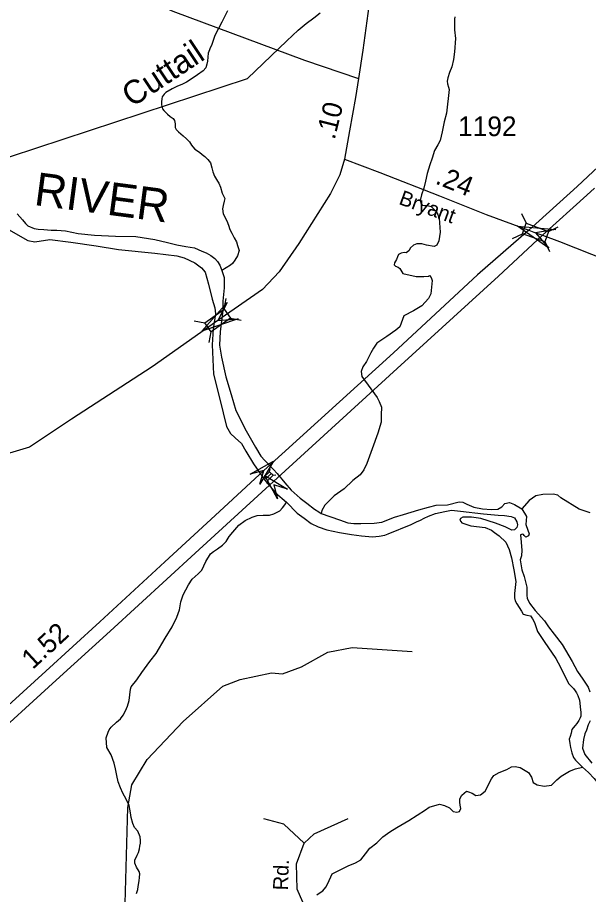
# Model space of a CAD drawing. Extents: x 2056842 to 2160602, y 826753 to 1016856.
# Drawn here: x 2102032 to 2105666, y 899934 to 905515 of the extents above; entities that cross this region are included whole.
import ezdxf

# ---------------------------------------------------------------- set-up
doc = ezdxf.new("R2010")
doc.units = 0
for name, color, linetype in [('Exist Hydrographic Creek Single Shore', 7, 'Continuous'), ('Exist Hydrographic Creek Single Shore Label', 7, 'Continuous'), ('Exist Hydrographic Misc Water Feature', 7, 'Continuous'), ('Exist Hydrographic River Shore', 7, 'Continuous'), ('Exist Hydrographic River Shore Label', 7, 'Continuous'), ('Exist Road Non-System Type 51', 7, 'Continuous'), ('Exist Road Non-System Type 51 Label', 7, 'Continuous'), ('Exist Road Primary Interstate Divided Center Attributed', 7, 'Continuous'), ('Exist Road Primary Interstate Mileage Hundredths English Label', 7, 'Continuous'), ('Exist Road Primary Interstate Structure Standard Bridge CELL', 7, 'Continuous'), ('Exist Road Secondary Mileage Hundredths English Label', 7, 'Continuous'), ('Exist Road Secondary Structure Standard Bridge Attributed CELL', 7, 'Continuous'), ('Exist Road Secondary Structure Standard Bridge CELL', 7, 'Continuous'), ('Exist Road Secondary Type 51 Attributed', 7, 'Continuous'), ('Exist Road Secondary Type 51 Label', 7, 'Continuous'), ('Exist Road Secondary Type 51 Number Label', 7, 'Continuous'), ('Exist Utilities Electrical Transmission Line', 7, 'Continuous')]:
    doc.layers.add(name, color=color, linetype=linetype)

msp = doc.modelspace()

# ---------------------------------------------------------------- linework, layer by layer
at = {"layer": 'Exist Hydrographic Creek Single Shore'}
for points in [[(2103369.4, 905558.8), (2103332, 905486.2), (2103288.3, 905400.8), (2103267.9, 905337.5), (2103258, 905321.6), (2103253.8, 905309.6), (2103245.8, 905287.4), (2103242.2, 905237.6), (2103238.1, 905217.4), (2103230.1, 905195.6), (2103214.3, 905175.6), (2103178.4, 905151.4), (2103144.4, 905127.1), (2103108.5, 905103.3), (2103078.6, 905089.1), (2103050.5, 905078.9), (2103016.7, 905060.9), (2102976.9, 905038.7), (2102964.8, 905026.5), (2102953, 905010.7), (2102950.8, 904998.6), (2102949, 904978.6), (2102949, 904958.6), (2102955, 904934.5), (2102963, 904922.5), (2102987.1, 904900.7), (2103003.2, 904884.9), (2103023.3, 904872.7), (2103031.3, 904860.7), (2103035.4, 904839), (2103035.6, 904815), (2103041.5, 904802.8), (2103057.6, 904787), (2103085.7, 904763.2), (2103107.6, 904743), (2103127.8, 904723.2), (2103139.9, 904703.3), (2103147.8, 904691.3), (2103160, 904677.3), (2103189.8, 904659.3), (2103207.9, 904643.5), (2103224, 904631.7), (2103244, 904611.6), (2103260.2, 904589.6), (2103268.1, 904557.6), (2103276.1, 904533.8), (2103286.4, 904505.7), (2103305.3, 904473.8), (2103314.3, 904461.8), (2103323.5, 904435.4), (2103335.2, 904397), (2103351.2, 904363.9), (2103348, 904345.7), (2103340.9, 904317.9), (2103337.3, 904296.7), (2103340.5, 904265.7), (2103365.2, 904221.9), (2103375.4, 904194.1), (2103383.4, 904166), (2103395.3, 904142.2), (2103411.4, 904112), (2103425.7, 904088.1), (2103431.8, 904064.3), (2103443, 904032.7), (2103432.3, 903998.5), (2103416.3, 903971.8), (2103400.3, 903950.4), (2103387.5, 903938.7), (2103333.1, 903905.6)], [(2104815.3, 905520.5), (2104813.3, 905504.5), (2104813.3, 905476.5), (2104813.1, 905435.8), (2104819.5, 905382.4), (2104813.1, 905297), (2104807.8, 905247.9), (2104796.3, 905200.5), (2104782.3, 905164.4), (2104770.4, 905132.4), (2104766.5, 905110.4), (2104768.6, 905092.4), (2104774.5, 905072.4), (2104780.5, 905056.4), (2104763.1, 904906.4), (2104747.3, 904852.3), (2104735.6, 904788.3), (2104721.6, 904732.2), (2104707.9, 904704.2), (2104685.8, 904668.2), (2104672, 904620.2), (2104656, 904578), (2104640.4, 904522.1), (2104628.5, 904474), (2104618.5, 904430), (2104602.9, 904385.9), (2104594.9, 904349.9), (2104598.8, 904333.9), (2104606.8, 904321.9), (2104623.2, 904319.2), (2104639.2, 904319.2), (2104665.8, 904312.8), (2104700, 904276.5), (2104714.9, 904239.1), (2104721.3, 904148.4), (2104713.9, 904093.9), (2104701.1, 904066.2), (2104684, 904058.7), (2104634.9, 904067.2), (2104605.6, 904074), (2104573.6, 904073.9), (2104551.9, 904065.8), (2104533.8, 904049.7), (2104521.9, 904029.7), (2104505.9, 904017.7), (2104493.8, 904019.7), (2104473.9, 904015.6), (2104457.9, 904007.6), (2104450.1, 903991.5), (2104444, 903975.5), (2104431.1, 903954.3), (2104430, 903941.5), (2104437.5, 903932.9), (2104454.6, 903925.5), (2104466.3, 903918), (2104485.5, 903887), (2104569.8, 903867.8), (2104618.9, 903867.8), (2104647.7, 903869.9), (2104655.2, 903873.1), (2104665.8, 903861.4), (2104671.2, 903841.1), (2104662.6, 903755.7), (2104648.8, 903727.9), (2104606.1, 903680.9), (2104553.1, 903647.9), (2104490.8, 903616.9), (2104465.2, 903546.4), (2104439.6, 903525.1), (2104383.1, 903484.5), (2104319.5, 903443.2), (2104297.7, 903411.9), (2104281.7, 903380.9), (2104254, 903325.4), (2104230.5, 903292.3), (2104219.8, 903261.3), (2104223, 903231.5), (2104322.2, 903096.9)], [(2104322.2, 903096.9), (2104334, 903072.4), (2104347.9, 903036.1), (2104346.8, 902987), (2104345.7, 902940), (2104325.4, 902869.7), (2104289.2, 902769.4), (2104255, 902677.5), (2104235.8, 902635.9), (2104212.3, 902603.9), (2104166.5, 902568.8), (2104111, 902516.5), (2104048, 902471.7), (2103988.3, 902411.9), (2103969.1, 902378.2), (2103965, 902358.2)], [(2103936.5, 899932.4), (2103958.6, 899946.5), (2103974.6, 899956.5), (2103994.3, 899980.6), (2104006.4, 900004.7), (2104034.1, 900064.7), (2104137.6, 900116.4), (2104183.5, 900135.6), (2104216.6, 900153.7), (2104246.5, 900192.2), (2104275.3, 900229.5), (2104319, 900262.6), (2104357.5, 900300), (2104401.3, 900331.8), (2104447.1, 900359.8), (2104523.1, 900404.1), (2104629.6, 900471.9), (2104652, 900489), (2104718.6, 900508.8), (2104750.5, 900500.9), (2104782.2, 900484.7), (2104805.6, 900461.2), (2104828, 900458), (2104845.1, 900462.3), (2104853.6, 900481.5), (2104850.4, 900502.9), (2104848.3, 900521), (2104848.3, 900543.4), (2104860.1, 900565.9), (2104888.9, 900590.4), (2104901.7, 900587.4), (2104925.1, 900577.8), (2104949.7, 900562.9), (2104979.6, 900568.2), (2105008.4, 900590.6), (2105048.9, 900669.6), (2105063.9, 900692.1), (2105098, 900710.2), (2105147.1, 900728.4), (2105177, 900745.4), (2105199.4, 900748.6), (2105231.4, 900741.2), (2105283.7, 900711.3), (2105304, 900681.4), (2105314.6, 900646.1), (2105339.2, 900631.2), (2105384, 900622.7), (2105430.9, 900630.1), (2105464, 900664.3), (2105491.8, 900686.7), (2105546.2, 900717.7), (2105584.6, 900732.6), (2105628.4, 900744.4)]]:
    msp.add_lwpolyline(points, dxfattribs=at)
at = {"layer": 'Exist Hydrographic Misc Water Feature'}
for points in [[(2105676.4, 902363.4), (2105606, 902385.8), (2105489.6, 902458.4), (2105470.4, 902474.5), (2105440.5, 902480.8), (2105375.5, 902478.7), (2105331.7, 902470), (2105288, 902441.2), (2105241, 902388.8)], [(2102788.6, 899940.9), (2102798.7, 899964.9), (2102800.5, 899984.9), (2102806.4, 900021), (2102808.3, 900041), (2102810.3, 900064.9), (2102806.4, 900080.8), (2102790, 900108.8), (2102780, 900132.8), (2102778.2, 900152.8), (2102793.9, 900184.9), (2102801.9, 900200.9), (2102807.9, 900224.9), (2102811.8, 900240.9), (2102815.7, 900261), (2102815.7, 900276.9), (2102813.6, 900300.9), (2102797.4, 900336.8), (2102777.3, 900360.7), (2102767.3, 900384.7), (2102755.2, 900424.7), (2102751.1, 900452.7), (2102742.9, 900500.6), (2102722.8, 900540.6), (2102702.7, 900578.5), (2102686.7, 900612.4), (2102672.5, 900650.5), (2102664.3, 900690.4), (2102656.4, 900734.3), (2102648.1, 900770.3), (2102628.1, 900822.2), (2102601.8, 900870.2), (2102595.7, 900930.2), (2102609.6, 900966.1), (2102615.5, 900982.1), (2102627.4, 900998.2), (2102663.3, 901030.3), (2102687.3, 901052.5), (2102705.2, 901074.4), (2102719.5, 901102.9), (2102732.3, 901132.8), (2102741.9, 901169.1), (2102750.4, 901239.6), (2102754.7, 901255.6), (2102792, 901299.4), (2102823, 901347.4), (2102875.3, 901416), (2102914.8, 901467.2), (2102971.3, 901565.4), (2103016.1, 901638), (2103047.1, 901697.8), (2103063.1, 901745.9), (2103072.7, 901796.1), (2103086.8, 901841.6), (2103120.6, 901905.6), (2103144.4, 901941.7), (2103182.3, 901973.9), (2103206.3, 901997.9), (2103230.1, 902053.9), (2103259.8, 902102), (2103279.9, 902116.2), (2103305.8, 902134.2), (2103335.9, 902156.3), (2103359.7, 902180.4), (2103379.6, 902212.4), (2103403.6, 902240.4), (2103441.3, 902284.6), (2103481.3, 902314.7), (2103526.2, 902335.7), (2103557.1, 902346.3), (2103596.6, 902348.5), (2103619, 902347.4), (2103636.1, 902348.5), (2103662.8, 902357), (2103701.1, 902375.4), (2103719.1, 902395.5), (2103732.9, 902413.5), (2103744.8, 902431.6)]]:
    msp.add_lwpolyline(points, dxfattribs=at)
at = {"layer": 'Exist Hydrographic River Shore'}
for points in [[(2102030.2, 904264.8), (2102064.3, 904227.4), (2102083.5, 904205), (2102098.5, 904190), (2102139, 904173), (2102163.5, 904168.7), (2102199.8, 904166.1), (2102246.8, 904161.9), (2102282, 904160.8), (2102337.5, 904158.6), (2102417.5, 904140.5), (2102523.1, 904130.9), (2102655.5, 904123.4), (2102784.6, 904121.3), (2102906.2, 904102.1), (2102987.3, 904083.9), (2103047.1, 904069), (2103103.6, 904058.3), (2103158.1, 904048.7), (2103205.9, 904027.7), (2103233.9, 904017.6), (2103261.8, 904001.6), (2103288, 903981.7), (2103306, 903961.9), (2103319.2, 903938.7), (2103333.1, 903905.6)], [(2101975.7, 904165.5), (2102097.4, 904097.1), (2102143.3, 904088.6), (2102237.2, 904101.4), (2102371.6, 904086.5), (2102533.8, 904063), (2102675.7, 904039.5), (2102906.2, 904014.9), (2103046, 903997.9), (2103091.9, 903986.1), (2103161.3, 903954.7), (2103202.9, 903922.7), (2103227.4, 903894.9), (2103248.8, 903818.1), (2103270.1, 903722.8), (2103288.2, 903667.3), (2103291.4, 903629.9), (2103276.5, 903533.8), (2103272.2, 903431.3), (2103279.7, 903244.9), (2103319.2, 903086.9), (2103362.9, 902911.8), (2103387.5, 902867), (2103417.4, 902839.2), (2103456.8, 902804.4), (2103484.6, 902755.3), (2103534.7, 902675.2), (2103607.3, 902570.6), (2103673.5, 902490.1), (2103744.8, 902431.6)], [(2103333.1, 903905.6), (2103346.9, 903860.8), (2103348, 903794.6), (2103338.4, 903709.2), (2103338.4, 903651.5), (2103322.4, 903516.8), (2103317.1, 903430.3), (2103329.9, 903353.4), (2103357.6, 903227.8), (2103392.8, 903116.8), (2103421.6, 903014.3), (2103486.7, 902884), (2103546.5, 902779.8), (2103580.1, 902722.9), (2103606.2, 902695.5), (2103661.7, 902638.9), (2103685.2, 902613.3), (2103733.2, 902554.1), (2103773.8, 902507.6), (2103830.9, 902455.7), (2103872.9, 902423.9), (2103923.2, 902386.1), (2103949, 902370.1), (2103965, 902358.2)], [(2103744.8, 902431.6), (2103813, 902361.7), (2103857.1, 902327.9), (2103901.4, 902294.1), (2103945.3, 902274.2), (2104001.3, 902254.4), (2104081.3, 902238.6), (2104157.9, 902224), (2104220.9, 902216.5), (2104291.3, 902210.1), (2104334, 902214.4), (2104369.4, 902221.5), (2104391.3, 902229.6), (2104537.1, 902288), (2104571.1, 902306.1), (2104597.2, 902316.2), (2104621.2, 902328.2), (2104649, 902342.4), (2104691.5, 902358.5), (2104722.4, 902366), (2104751.2, 902372.4), (2104795, 902378.8), (2104851.5, 902372.8), (2104997.7, 902355.7), (2105090.5, 902348.3), (2105132.2, 902345.1), (2105173.8, 902338.7), (2105195.1, 902330.1), (2105211.1, 902305.6), (2105215, 902286.1), (2105210.1, 902270.3), (2105195.1, 902255.4), (2105178.1, 902253.2), (2105136.4, 902273.5), (2105073.5, 902298.1), (2105028.7, 902313), (2104980.6, 902325.8), (2104920.9, 902335.5), (2104866.5, 902334.4), (2104852.6, 902326.9), (2104847.3, 902315.2), (2104860.1, 902300.2), (2104916.6, 902281), (2105008.4, 902269.3), (2105047.9, 902252.2), (2105067.1, 902238.3), (2105098, 902216.9), (2105139.6, 902175.3), (2105162, 902129), (2105175.9, 902075.6), (2105190.9, 901999.8), (2105204.7, 901925), (2105194.5, 901850.1), (2105194.5, 901822.1), (2105198.6, 901802.1), (2105211.1, 901783.7), (2105238.9, 901737.8), (2105250.6, 901718.8), (2105273, 901711.3), (2105296.5, 901707), (2105310.4, 901688.6), (2105323.2, 901664.1), (2105342.4, 901607.7), (2105384, 901544.7), (2105457.8, 901434.9), (2105487.9, 901381.1), (2105516, 901323.1), (2105542, 901275.3), (2105570.7, 901244.5)], [(2103965, 902358.2), (2104082.2, 902317.9), (2104134.4, 902299.8), (2104172.9, 902295.5), (2104217.7, 902295.5), (2104302, 902297.7), (2104351.1, 902304.1), (2104431.1, 902335), (2104489.8, 902353.2), (2104586.9, 902382), (2104647.7, 902399.1), (2104696.8, 902410.8), (2104768.3, 902414), (2104843, 902432.2), (2104867.5, 902430.5), (2104892.1, 902417.7), (2104936.9, 902399.5), (2104991.3, 902387.8), (2105048.9, 902384.6), (2105088.4, 902385.6), (2105115.1, 902401.6), (2105133.2, 902421.9), (2105163.1, 902428.3), (2105196.2, 902415.5), (2105241, 902388.8)], [(2105241, 902388.8), (2105270.9, 902339.7), (2105267.7, 902288.5), (2105280.5, 902253.2), (2105288, 902228.7), (2105283.7, 902215.9), (2105266.6, 902208.4), (2105257.2, 902217.9), (2105253.1, 902225.9), (2105245.2, 902228), (2105233.3, 902222), (2105235.1, 902200), (2105241, 902125.8), (2105239.9, 902089.5), (2105231.4, 902062.8), (2105241.8, 902000.1), (2105256, 901958.1), (2105274.1, 901890.4), (2105273, 901836), (2105275.2, 901818.9), (2105291.2, 901789), (2105326.4, 901741), (2105386.1, 901676), (2105410.7, 901637.6), (2105447, 901590.6), (2105499.2, 901525.5), (2105561.5, 901417.3), (2105595.9, 901353.2), (2105629.4, 901305.3), (2105663.6, 901254.1), (2105674.2, 901223.1)], [(2105570.7, 901244.5), (2105582.5, 901229.5), (2105588.9, 901216.7), (2105597.4, 901199.6), (2105609.2, 901169.7), (2105614.6, 901109.5), (2105616.9, 901093.5), (2105616.9, 901069.5), (2105612.8, 901057.5), (2105604.8, 901041.4), (2105591.1, 901021.4), (2105581, 901009.3), (2105569.1, 900995.4), (2105561.1, 900983.3), (2105555.2, 900961.3), (2105549.4, 900939.3), (2105543.3, 900923.3), (2105547.4, 900895.3), (2105551.3, 900869.3), (2105559.7, 900835.3), (2105571.6, 900805.4), (2105583.7, 900789.4), (2105601.9, 900769.5), (2105628.4, 900744.4)], [(2105677.4, 901039.1), (2105664.6, 901014.5), (2105652.8, 900979.3), (2105643.1, 900955.6), (2105634.8, 900920.5), (2105627.3, 900866.1), (2105642.2, 900824.5), (2105688.1, 900770)], [(2105628.4, 900744.4), (2105666.8, 900711.3), (2105703, 900671.8), (2105748.1, 900611.9), (2105768.4, 900582), (2105897.3, 900415.3), (2105934.6, 900373.7)]]:
    msp.add_lwpolyline(points, dxfattribs=at)
at = {"layer": 'Exist Road Non-System Type 51'}
for points in [[(2102699.4, 898727.5), (2102699.4, 898827.1), (2102694.9, 899158.1), (2102716.5, 899877.3), (2102735.1, 900487.7), (2102760.5, 900632.2), (2102856.5, 900794), (2103087.4, 901035.4), (2103339.9, 901259.8), (2103450.1, 901303), (2103648.2, 901344.7), (2103718.3, 901337.3), (2103838.9, 901382), (2104006.5, 901475.2), (2104161.4, 901505), (2104544.2, 901479.6)], [(2103856.8, 900259.6), (2103727.2, 900381.8), (2103599.1, 900414.6)], [(2103856.8, 900259.6), (2103920.8, 900319.2), (2104136.8, 900417.6)], [(2104006.5, 899595.5), (2103940.9, 899723.7), (2103862, 899850.4), (2103812.8, 899968.2), (2103807.6, 900129.9), (2103856.8, 900259.6)]]:
    msp.add_lwpolyline(points, dxfattribs=at)
at = {"layer": 'Exist Road Primary Interstate Divided Center Attributed'}
for points in [[(2105828.7, 904661.1), (2105594.6, 904440.5), (2105287.1, 904161)], [(2105373.3, 904129.5), (2105655.7, 904384.7), (2105703.8, 904430.2)], [(2105287.1, 904161), (2104960.2, 903877), (2104425.8, 903381.9), (2103600.7, 902632.7)], [(2103660.8, 902561.3), (2104449.2, 903281.1), (2105093.4, 903869.8), (2105373.3, 904129.5)], [(2103600.7, 902632.7), (2103289.4, 902345), (2102970.9, 902051.5), (2102555.2, 901669.9), (2102213.3, 901354.8), (2101753.5, 900939), (2100980.6, 900231.5), (2100459.7, 899759.8), (2100051.2, 899387.1), (2099654.4, 899021.7), (2099369.7, 898762.5)], [(2099487.6, 898757.1), (2099760.5, 898998.3), (2100355.3, 899542), (2101025.6, 900154), (2101811.1, 900874.2), (2102278.1, 901297.2), (2102621.8, 901610.5), (2103163.4, 902105.5), (2103660.8, 902561.3)]]:
    msp.add_lwpolyline(points, dxfattribs=at)
at = {"layer": 'Exist Road Primary Interstate Structure Standard Bridge CELL'}
for p, q in [((2103637, 902624.8), (2103640.5, 902643.3)), ((2103584, 902589.3), (2103602.7, 902592)), ((2103613.6, 902580.6), (2103647.9, 902613.4)), ((2103621.1, 902550.6), (2103624.6, 902569.2)), ((2103658.6, 902602.2), (2103677.3, 902604.9))]:
    msp.add_line(p, q, dxfattribs=at)
msp.add_lwpolyline([(2103624.6, 902569.2), (2103658.8, 902602), (2103637, 902624.8), (2103602.7, 902592)], close=True, dxfattribs=at)
at = {"layer": 'Exist Road Secondary Structure Standard Bridge Attributed CELL'}
for points in [[(2105414, 904047), (2105214.9, 904187.7), (2105457.7, 904165.4), (2105329.3, 904145.5)], [(2103437.2, 903596.6), (2103206.1, 903518.8), (2103367.4, 903701.7), (2103307.7, 903586.3)], [(2103512.8, 902609.4), (2103662.3, 902691.8), (2103574, 902545.7), (2103600.7, 902632.7)], [(2103687.8, 902452), (2103605.5, 902601.5), (2103751.5, 902513.2), (2103664.6, 902540)]]:
    msp.add_lwpolyline(points, close=True, dxfattribs=at)
at = {"layer": 'Exist Road Secondary Structure Standard Bridge CELL'}
for p, q in [((2105240.5, 904267.9), (2105269.7, 904205.4)), ((2105183.2, 904109.8), (2105245.7, 904139.1)), ((2105411.7, 904153.7), (2105474.2, 904182.9)), ((2105388.2, 904088.8), (2105417.4, 904026.3)), ((2103348.4, 903658.4), (2103360.4, 903726.3)), ((2103156.4, 903584.1), (2103224.4, 903572.1)), ((2103387.9, 903601.9), (2103455.9, 903589.8)), ((2103252.8, 903446.3), (2103264.8, 903514.2))]:
    msp.add_line(p, q, dxfattribs=at)
for points in [[(2105269.7, 904205.4), (2105411.8, 904154), (2105387.8, 904087.6), (2105245.7, 904139.1)], [(2103224.4, 903572.1), (2103348.2, 903658.7), (2103388.7, 903600.8), (2103264.8, 903514.2)]]:
    msp.add_lwpolyline(points, close=True, dxfattribs=at)
at = {"layer": 'Exist Road Secondary Type 51 Attributed'}
for points in [[(2099852.1, 911588.7), (2099911.7, 911448.2), (2100030.3, 911099.4), (2100210.8, 910573.6), (2100321.3, 910162.8), (2100454.3, 909815.9), (2100658.2, 909234.3), (2100869.2, 908654.6), (2100991.4, 908309.4), (2101164.7, 907792.6), (2101361.4, 907238), (2101435.1, 907083.4), (2101537.5, 906912.6), (2101734.2, 906658.2), (2102071.9, 906295.1), (2102423.1, 905907.7), (2102599.2, 905769.3), (2102771.6, 905666.8), (2103021.3, 905555.3), (2103859.4, 905243.4), (2104202.5, 905126.6)], [(2107717.1, 910459.4), (2107551, 910309.3), (2106924.9, 909672.1), (2106491.1, 909225.3), (2106300.7, 909022.2), (2106178.5, 908882), (2106101.3, 908768.7), (2105911.7, 908402.9), (2105789.6, 908221.3), (2105728.5, 908151.2), (2105310.9, 907819.5), (2105125.8, 907647), (2104960.5, 907447.4), (2104807, 907254.2), (2104713.5, 907110.3), (2104621.9, 906923.4), (2104524.9, 906713.1), (2104473.7, 906562.9), (2104410.8, 906313.1), (2104268, 905587.7), (2104230.3, 905307.3), (2104202.5, 905126.6)], [(2104202.5, 905126.6), (2104183.6, 905006.1), (2104145.4, 904794.5), (2104113.5, 904613.3)], [(2104113.5, 904613.3), (2104083.4, 904514.9), (2104024.2, 904394.5), (2103822.1, 904077.2), (2103698.1, 903897.4), (2103592.1, 903784.2), (2103307.7, 903586.3)], [(2104113.5, 904613.3), (2104338.5, 904529.3), (2104717.6, 904380.1), (2105014, 904261.5), (2105287.1, 904161)], [(2105373.3, 904129.5), (2105482.1, 904089.8), (2105979.7, 903892.1), (2106494.4, 903691.7), (2106877, 903555), (2107018.9, 903520.9), (2107160.9, 903502.9), (2107307.3, 903491.2), (2107946.8, 903460.6), (2108547.7, 903438.2), (2108916, 903449), (2109022, 903456.2), (2109158.5, 903484.9), (2109494.4, 903607.2), (2109917.5, 903728.5), (2110398.9, 903857.9), (2110663, 903906.5), (2110823.8, 903964.9), (2111285.5, 904186), (2111639.4, 904355), (2111809.1, 904411.6), (2111897.1, 904436.8), (2111958.1, 904439.3)], [(2105287.1, 904161), (2105329.3, 904145.5), (2105373.3, 904129.5)], [(2103307.7, 903586.3), (2102888.8, 903292.5), (2102376, 902959), (2102108.3, 902781.1), (2101939.4, 902730.7), (2101681.7, 902675.9), (2101417.6, 902627.4), (2101196.6, 902622), (2101083.5, 902645.3), (2100814.9, 902739.7), (2100466.4, 902879.9), (2100276, 902941.1), (2100099.9, 902964.4), (2099929.3, 902951.8), (2099739.7, 902902.4), (2099362.5, 902787.3), (2099089.4, 902668.7), (2098715.8, 902395.5), (2098315.2, 902019.7), (2097934.4, 901678.2), (2097584.5, 901381.1)]]:
    msp.add_lwpolyline(points, dxfattribs=at)
at = {"layer": 'Exist Utilities Electrical Transmission Line'}
msp.add_lwpolyline([(2101483, 904465.3), (2103496.6, 905127.5), (2103745.8, 905366.2), (2103817.6, 905434.5), (2103869.5, 905476.7), (2103917.2, 905512.7), (2103959.3, 905544.8)], dxfattribs=at)

# ---------------------------------------------------------------- texts
at = {"layer": 'Exist Hydrographic Creek Single Shore Label'}
msp.add_text('Cuttail', height=150, rotation=33.4549, dxfattribs=at).set_placement((2102760.2, 904940.3))
at = {"layer": 'Exist Hydrographic River Shore Label'}
msp.add_text('RIVER', height=210, rotation=352.4384, dxfattribs=at).set_placement((2102131.9, 904322.9))
at = {"layer": 'Exist Road Non-System Type 51 Label'}
msp.add_text('Rd.', height=95, rotation=88.0751, dxfattribs=at).set_placement((2103753.1, 899959.1))
at = {"layer": 'Exist Road Primary Interstate Mileage Hundredths English Label'}
msp.add_text('1.52', height=125, rotation=42.659, dxfattribs=at).set_placement((2102129.1, 901362.2))
at = {"layer": 'Exist Road Secondary Mileage Hundredths English Label'}
for s, rotation, p in [('.10', 75.9145, (2104050.2, 904733)), ('.24', 338.1845, (2104685.4, 904460.3))]:
    msp.add_text(s, height=125, rotation=rotation, dxfattribs=at).set_placement(p)
at = {"layer": 'Exist Road Secondary Type 51 Label'}
msp.add_text('Bryant', height=95, rotation=339.9575, dxfattribs=at).set_placement((2104453.6, 904329.3))
at = {"layer": 'Exist Road Secondary Type 51 Number Label'}
msp.add_text('1192', height=125, dxfattribs=at).set_placement((2104836.3, 904760.5))

doc.saveas('drawing.dxf')
